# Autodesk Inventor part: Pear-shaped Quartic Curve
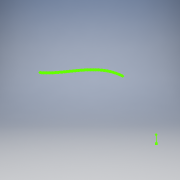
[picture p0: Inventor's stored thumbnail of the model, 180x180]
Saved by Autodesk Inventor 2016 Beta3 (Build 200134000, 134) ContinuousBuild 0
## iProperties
Created: 2008-02
Part Number: Pear-shaped Quartic Curve
Document SubType Name: Modeling
Designer: Autodesk, Inc.
Density: 1 g/cm^3
Material: Generic
Appearance: Default
Author: Autodesk, Inc.
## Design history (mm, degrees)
sketch "Sketch1"
  geometry: 301 further points
  constraints: 301 other
